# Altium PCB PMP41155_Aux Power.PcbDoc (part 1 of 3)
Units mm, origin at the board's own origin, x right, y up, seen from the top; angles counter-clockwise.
Board outline 40.5 x 70.5 mm, 6 copper layers (Top Layer, Signal Layer 1, Signal Layer 2, Signal Layer 3, Signal Layer 4, Bottom Layer), stack 1.573 mm thick; 130 components, 63 nets, 392 pads, 295 vias.
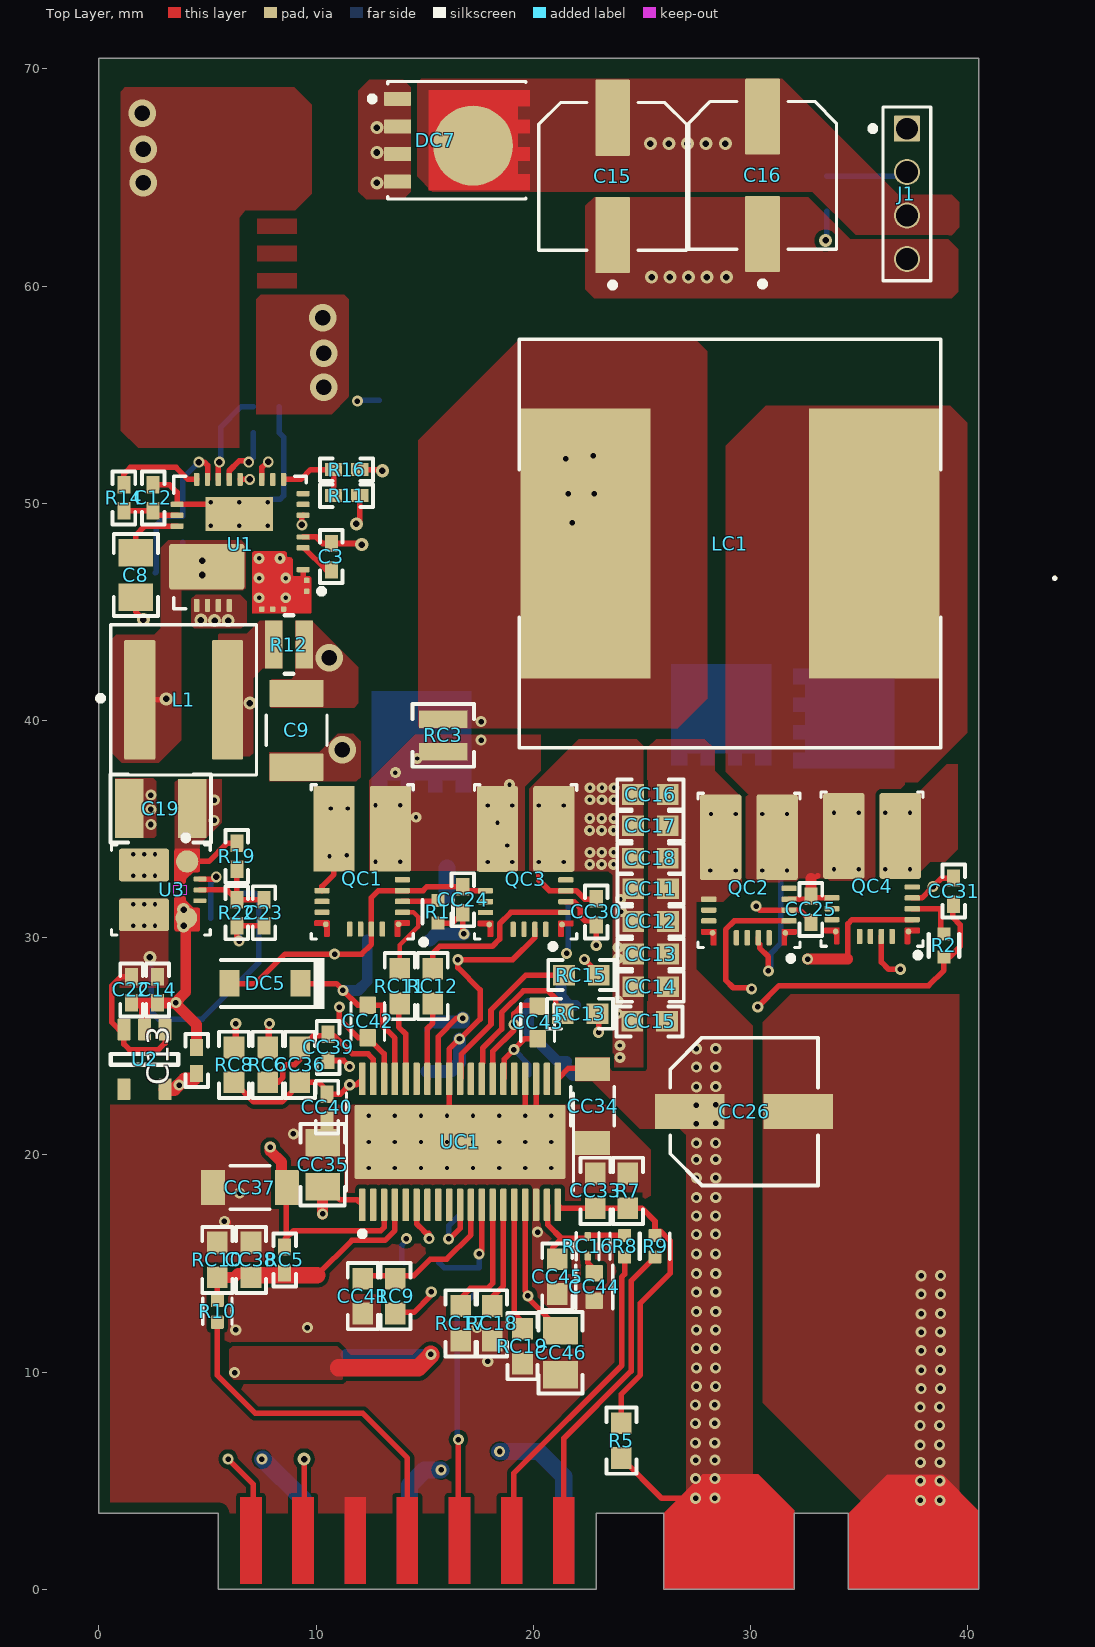
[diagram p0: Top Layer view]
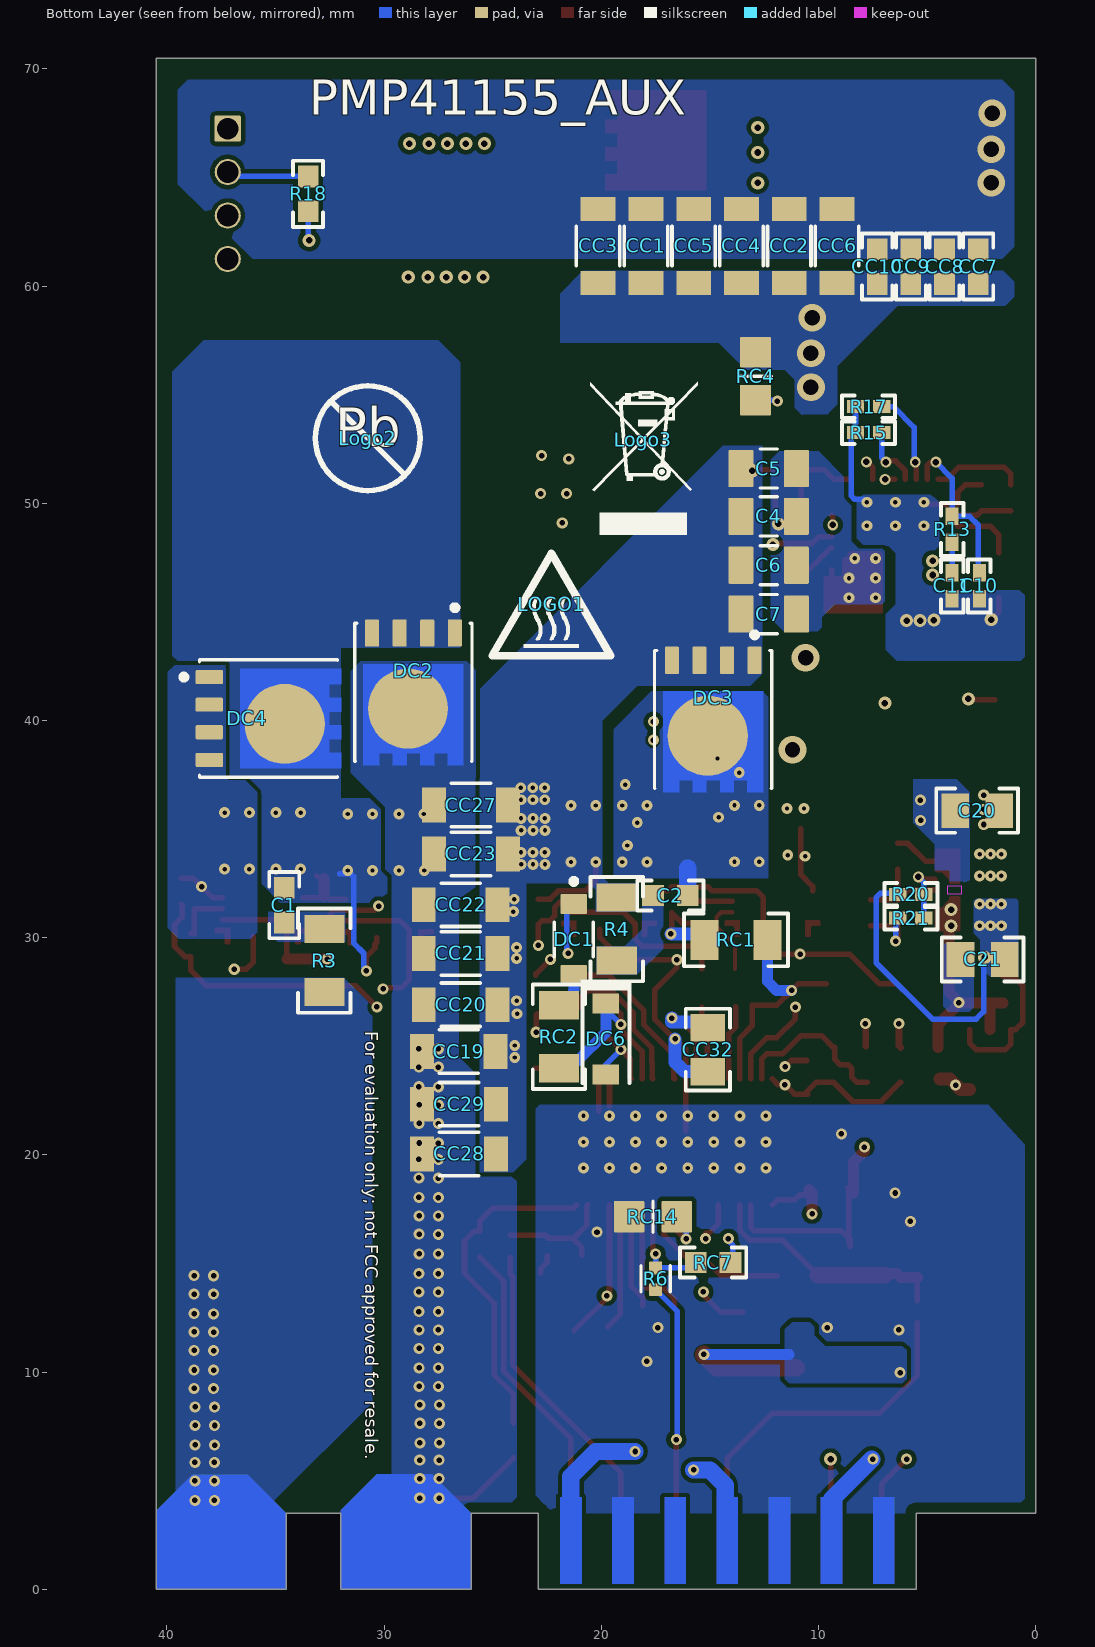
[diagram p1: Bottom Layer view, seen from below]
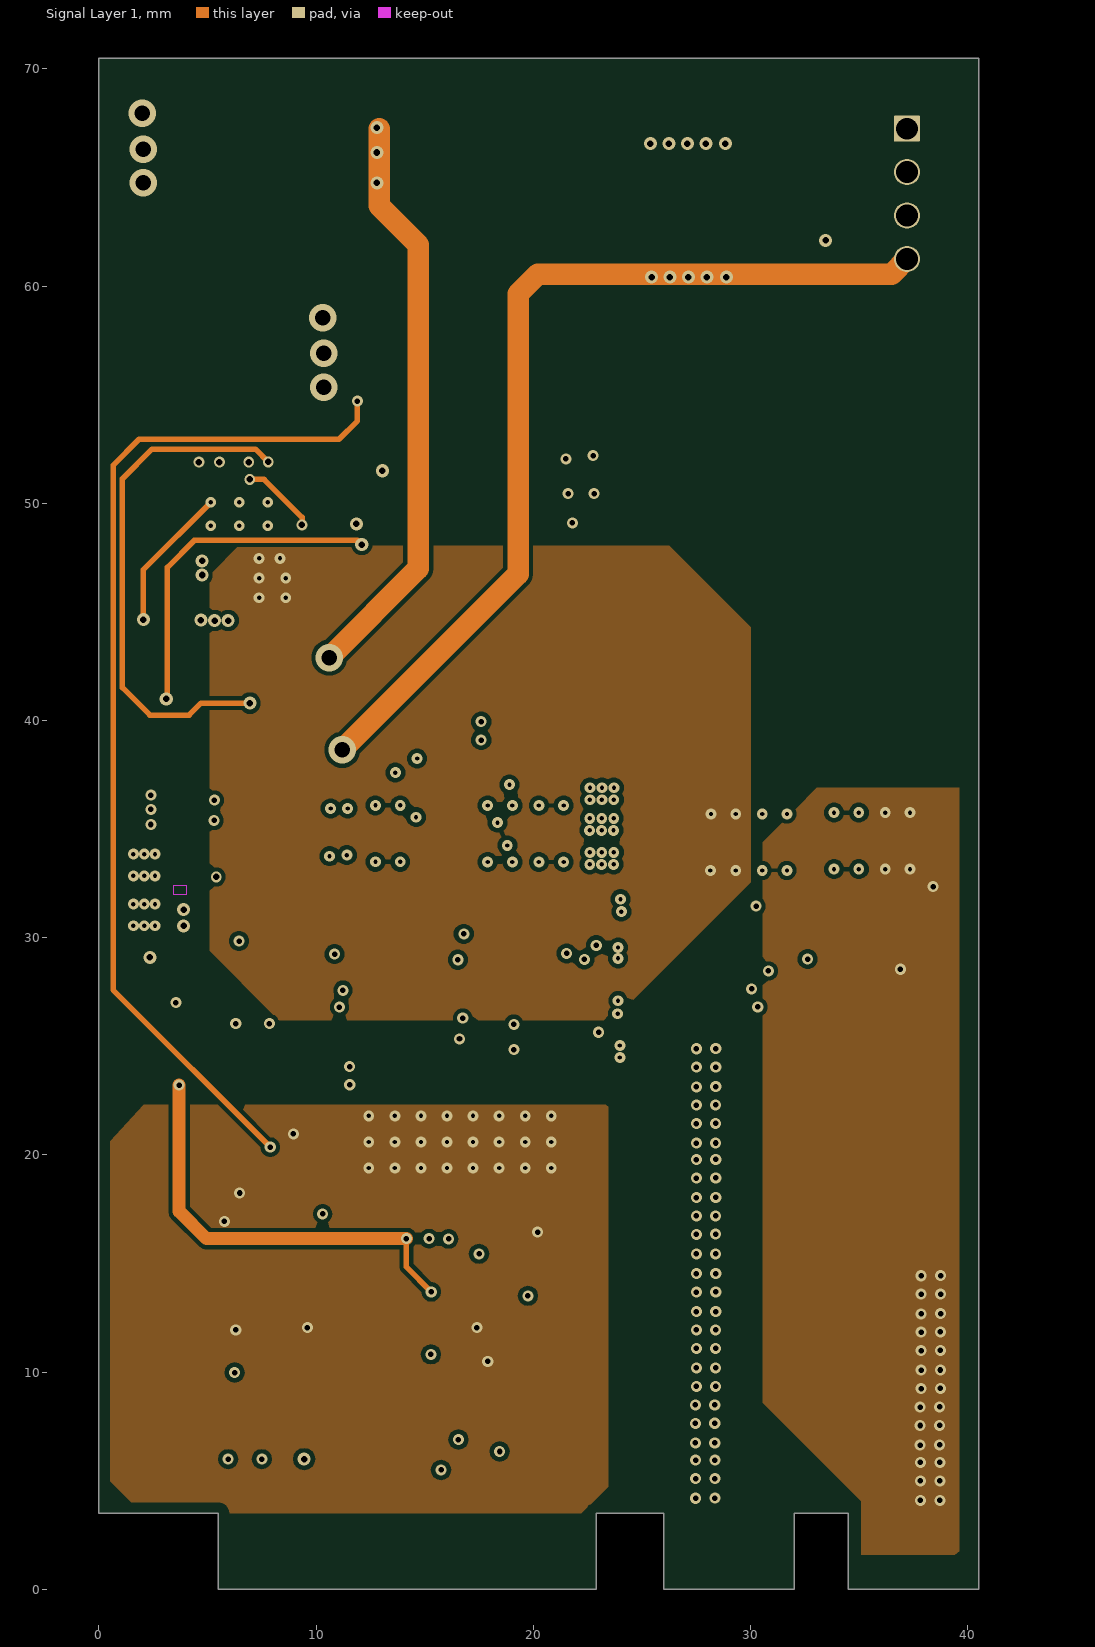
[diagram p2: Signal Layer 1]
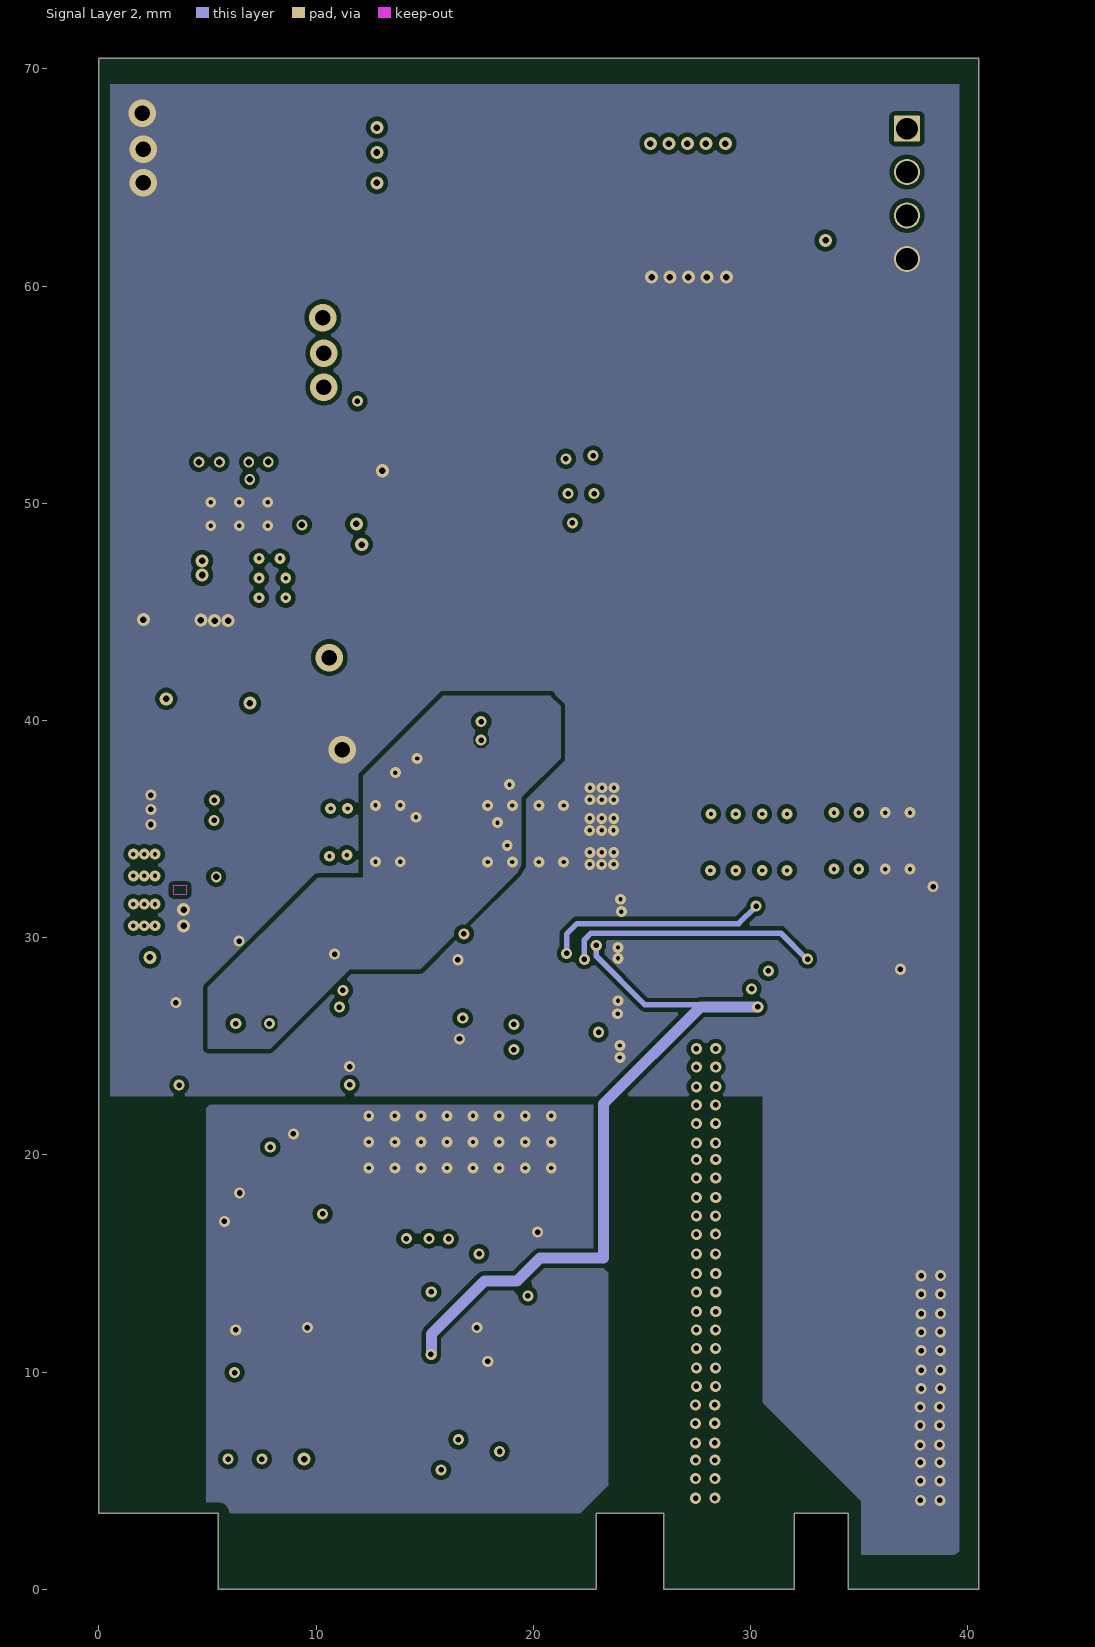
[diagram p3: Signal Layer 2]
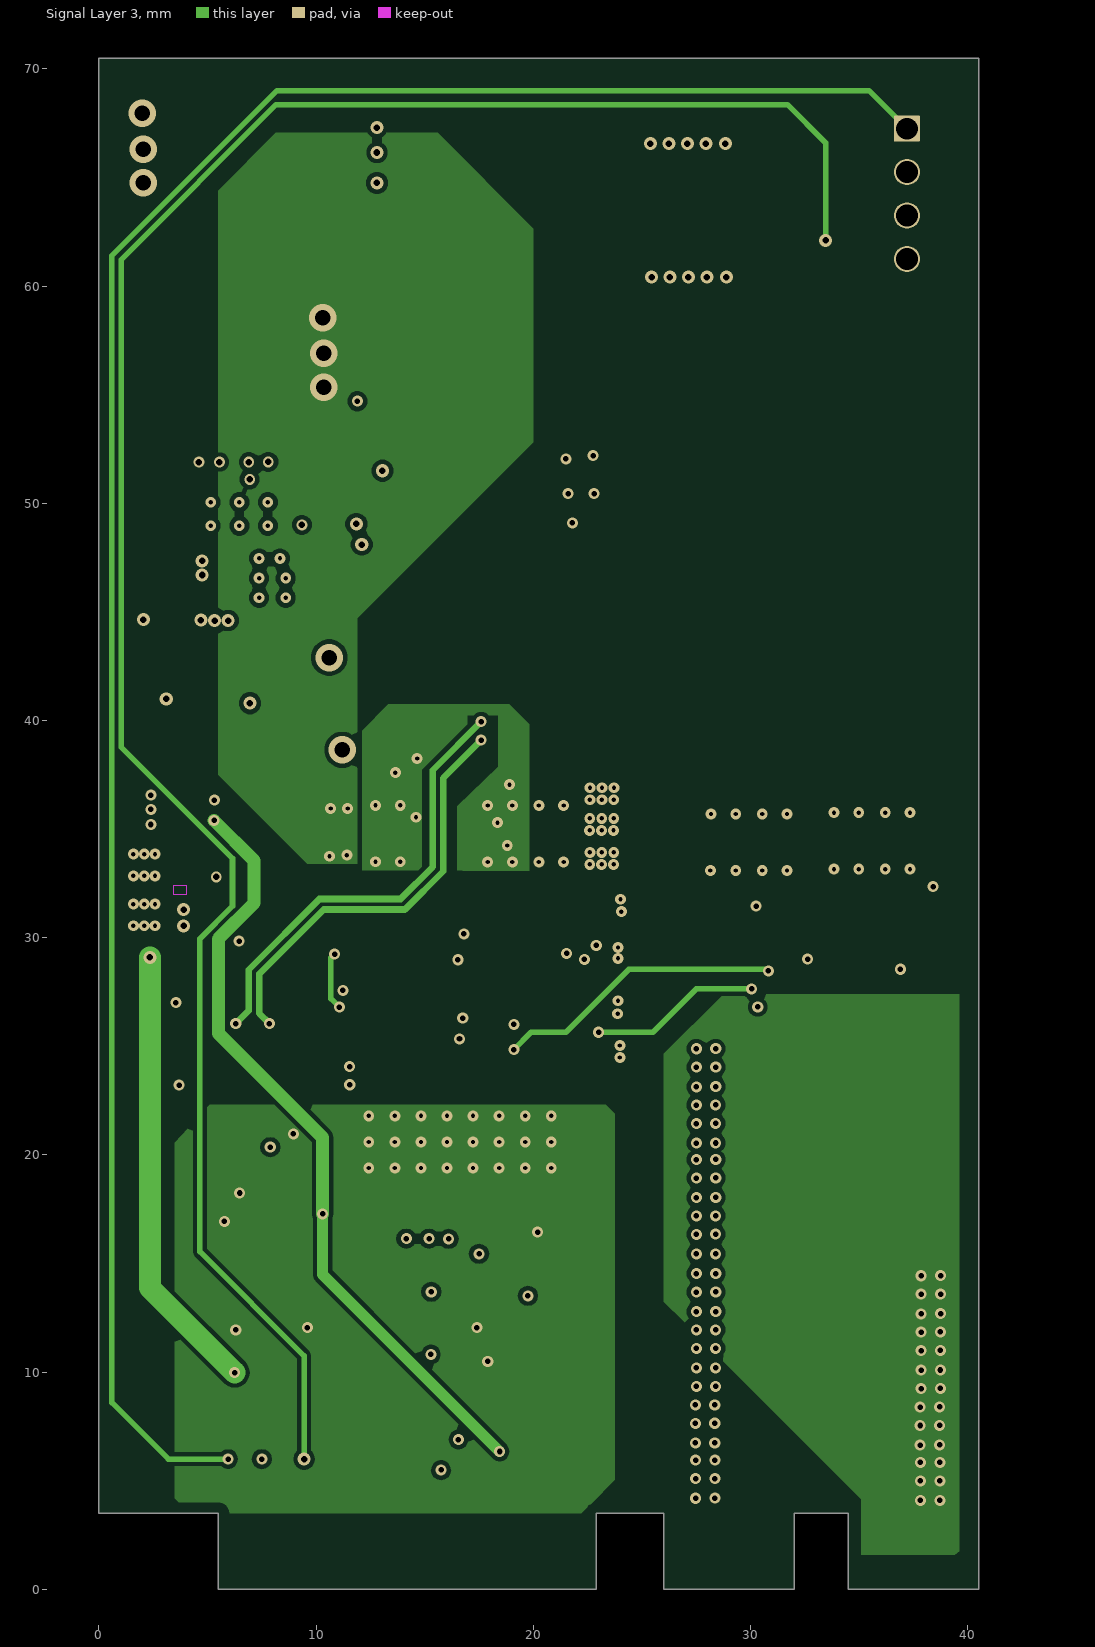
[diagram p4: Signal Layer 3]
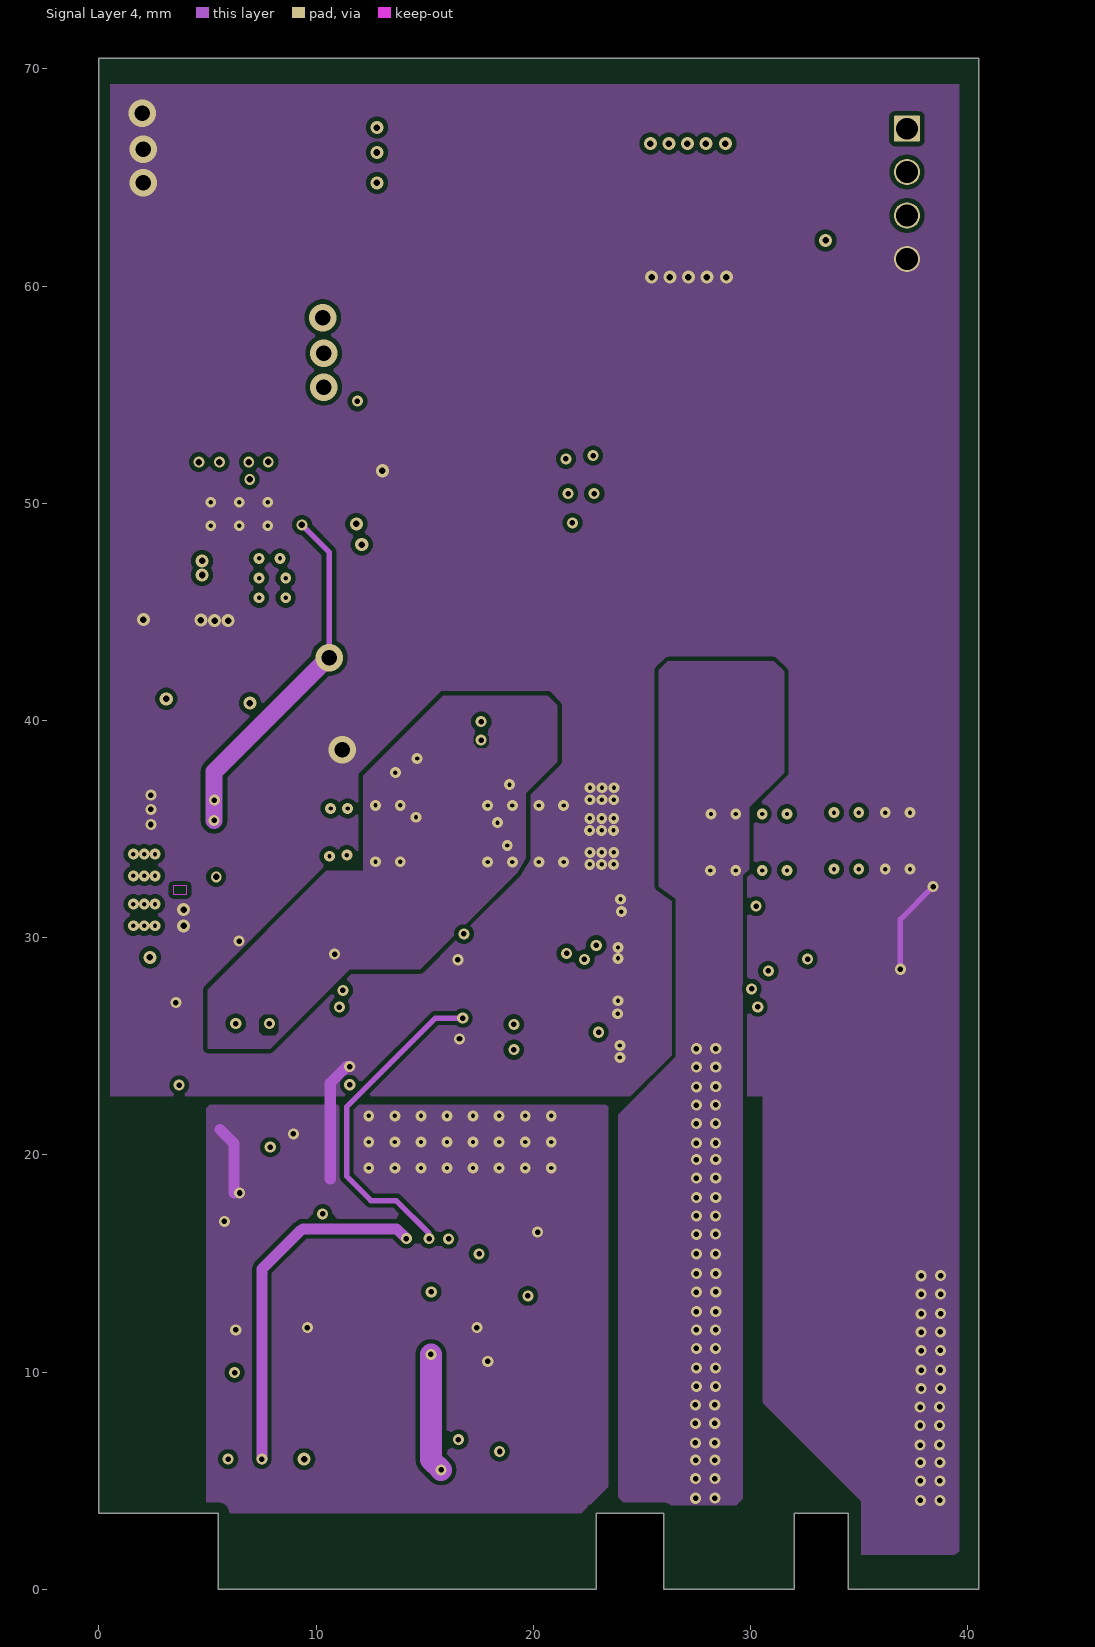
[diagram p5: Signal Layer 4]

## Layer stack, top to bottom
Top Solder: solder mask 0.01, Solder Resist, Dk 3.5
Top Layer: signal copper 0.07
Dielectric 1: prepreg 0.2, FR-4, Dk 4.2
Signal Layer 1: signal copper 0.07
Dielectric 4: core 0.2, FR-4, Dk 4.2
Signal Layer 2: signal copper 0.07
Dielectric 2: core 0.2, FR-4, Dk 4.2
Signal Layer 3: signal copper 0.07
Dielectric1: core 0.2032, Core-025, Dk 4.6
Signal Layer 4: signal copper 0.07
Dielectric 3: prepreg 0.35, Dk 4.2
Bottom Layer: signal copper 0.07
Bottom Solder: solder mask 0.01, Solder Resist, Dk 3.5

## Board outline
0,3.5 5.5,3.5 5.5,0 22.9,0 22.9,3.5 26,3.5 26,0 32,0 32,3.5 34.5,3.5 34.5,0 40.5,0 40.5,70.5 0,70.5

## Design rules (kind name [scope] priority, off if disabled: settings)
AcuteAngle [All] p1: minimum=4.50000000000000E+0001 checktracksonly=FALSE
AssemblyTestPointUsage [All] p1: valid=2
BoardOutlineClearance BoardOutlineClearance_MountingHoles [OnCopper and InComponentClass('Mounting Holes')] p1: gap=1.016 ignorepadtopadclearanceinfootprint=FALSE
BoardOutlineClearance BoardOutlineClearance_Poly [OnCopper and IsPoly] p2: gap=0.508 ignorepadtopadclearanceinfootprint=FALSE
BoardOutlineClearance [OnCopper and Not InComponentClass('Logo') and not InComponentClass('FiducialMark') and not InRegion(1000,500,4000,800) and not InPoly] p3: gap=0.254 ignorepadtopadclearanceinfootprint=FALSE
Clearance Clearance_1 [InNetClass('HV') vs Not InNetClass('HV')] p1: gap=0.508 ignorepadtopadclearanceinfootprint=FALSE
Clearance Clearance_Keepouts [((IsTrack Or IsArc) And Not InPoly) And IsFree and IsKeepOut vs ((IsTrack Or IsArc) And Not InPoly) And IsFree and IsKeepOut] p2: gap=0 ignorepadtopadclearanceinfootprint=FALSE
Clearance Clearance_Poly [InPolygon] p3: gap=0.2 ignorepadtopadclearanceinfootprint=FALSE
Clearance Clearance_FiducialMark [IsKeepOut and InComponentClass('FiducialMark') vs IsPad and InComponentClass('FiducialMark')] p4: gap=0 ignorepadtopadclearanceinfootprint=FALSE
Clearance [All] p5: gap=0.178 ignorepadtopadclearanceinfootprint=FALSE except(0.1: Via-Via Via-Fill Via-Poly Via-Region Via-Text Via-Hole)
ComponentClearance ComponentClearance_MountingHoles_FiducialMarks [InComponentClass('Mounting Holes') vs InComponentClass('FiducialMark')] p1: gap=1.27 collisioncheckmode=3 verticalgap=0.254 showdistances=FALSE
ComponentClearance ComponentClearance_Shunt [InComponentClass('Header') vs InComponentClass('Shunt')] p2: gap=0 collisioncheckmode=3 verticalgap=0 showdistances=FALSE
ComponentClearance ComponentClearance_Logo [InComponentClass('Logo')] p3: gap=1.27 collisioncheckmode=3 verticalgap=0.254 showdistances=FALSE
ComponentClearance ComponentClearance_ScrewToNut [(HasFootprint('NY PMS 440 0025 PH')) vs (HasFootprint('Keystone_1902C'))] p4: gap=0.127 collisioncheckmode=3 verticalgap=0.254 showdistances=FALSE
ComponentClearance ComponentClearance_MountingHoles [InComponentClass('Mounting Holes')] p5: gap=6.35 collisioncheckmode=3 verticalgap=2540 showdistances=FALSE
ComponentClearance ComponentClearance_SmallPassives [HasFootprint('0201*') or HasFootprint('0402*') or HasFootprint('0508') or HasFootprint('0603*') or HasFootprint('0612') or HasFootprint('0805*') or HasFootprint('0815*') or HasFootprint('0830*') or HasFootprint('1206*') or HasFootprint('1210*') or HasFootprint('1808*') or HasFootprint('1812*') or HasFootprint('1825*') or HasFootprint('2010*') or HasFootprint('2220*') or HasFootprint('2225*') or HasFootprint('2512*') or HasFootprint('2728*') or HasFootprint('3518*') vs HasFootprint('0201*') or HasFootprint('0402*') or HasFootprint('0508') or HasFootprint('0603*') or HasFootprint('0612') or HasFootprint('0805*') or HasFootprint('0815*') or HasFootprint('0830*') or HasFootprint('1206*') or HasFootprint('1210*') or HasFootprint('1808*') or HasFootprint('1812*') or HasFootprint('1825*') or HasFootprint('2010*') or HasFootprint('2220*') or HasFootprint('2225*') or HasFootprint('2512*') or HasFootprint('2728*') or HasFootprint('3518*')] p6: gap=0.254 collisioncheckmode=3 verticalgap=0.254 showdistances=FALSE
ComponentClearance ComponentClearance_THtoSMT [IsThruComponent vs IsSMTComponent] p7: gap=1.016 collisioncheckmode=3 verticalgap=0.762 showdistances=FALSE
ComponentClearance ComponentClearance_THtoTH [IsThruComponent vs IsThruComponent] p8: gap=0.508 collisioncheckmode=3 verticalgap=0.508 showdistances=FALSE
ComponentClearance [All] p9: gap=0.254 collisioncheckmode=3 verticalgap=0.254 showdistances=FALSE
DiffPairsRouting [All] p1: maxlimit=2.54 minlimit=0.254 mostfreqgap=0.254 toplayer_minwidth=0.381 toplayer_maxwidth=0.381 toplayer_prefwidth=0.381 midlayer1_minwidth=0.381 midlayer1_maxwidth=0.381 midlayer1_prefwidth=0.381 midlayer2_minwidth=0.381 midlayer2_maxwidth=0.381 midlayer2_prefwidth=0.381 midlayer3_minwidth=0.381 midlayer3_maxwidth=0.381 midlayer3_prefwidth=0.381 midlayer4_minwidth=0.381 midlayer4_maxwidth=0.381 midlayer4_prefwidth=0.381 bottomlayer_minwidth=0.381 bottomlayer_maxwidth=0.381 bottomlayer_prefwidth=0.381 maxuncoupledlength=25.4
FabricationTestPointUsage TestPointUsage [All] p1: valid=2 allowmultiple=FALSE
FabricationTestpoint Testpoint [All] p1: side=3 testpointundercomponent=TRUE minsize=1.016 maxsize=2.54 preferedsize=1.524 minholesize=0 maxholesize=1.016 preferedholesize=0.813 testpointgrid=0.025 allowsidetop=TRUE allowsidebottom=TRUE usegrid=TRUE gridtolerance=0
FanoutControl Fanout_LCC [IsLCC] p1: bgadir=Out bgaviamode=Centered fanoutstyle=Auto fanoutdirection=Alternating viagrid=0.025 // Fanout_LCC (Default Rule)
FanoutControl Fanout_BGA [IsBGA] p2: bgadir=Out bgaviamode=Centered fanoutstyle=Auto fanoutdirection=Alternating viagrid=0.025 // Fanout_BGA (Default Rule)
FanoutControl Fanout_Default [All] p4: bgadir=Out bgaviamode=Centered fanoutstyle=Auto fanoutdirection=Alternating viagrid=0.025 // Fanout_Default (Default Rule)
FanoutControl Fanout_Small [(CompPinCount < 5)] p5: bgadir=Out bgaviamode=Centered fanoutstyle=Auto fanoutdirection=OutThenIn viagrid=0.025 // Fanout_Small (Default Rule)
HoleSize [All] p1: absolutevalues=TRUE maxlimit=6.375 minlimit=0.2 maxpercent=80.000 minpercent=20.000
MinimumAnnularRing MinimumAnnularRing_ThermalPadVias [IsVia and InAnyComponent] p1: minimumring=0.15
MinimumAnnularRing [All] p2: minimumring=0.127
MinimumSolderMaskSliver MinimumSolderMaskSliver_Logo [InComponentClass('Logo') vs InComponentClass('Logo')] p1: minsoldermaskwidth=0.018
MinimumSolderMaskSliver [All] p2: minsoldermaskwidth=0.1
PlaneConnect [All] p1: planeconnectstyle=Direct reliefexpansion=0.254 reliefentries=4 reliefconductorwidth=0.254 reliefairgap=0.254
PolygonConnect PolygonConnect_19 [All vs IsNamedPolygon('SGND') Or  IsNamedPolygon('SGND') Or  IsNamedPolygon('SGND') Or  IsNamedPolygon('SW2') Or  IsNamedPolygon('VBAT_DISCH_IN') Or  IsNamedPolygon('VBAT_DISCH_IN') Or  IsNamedPolygon('VBAT_DISCH_IN') Or  IsNamedPolygon('CSB_DISCH') Or  IsNamedPolygon('SGND') Or  IsNamedPolygon('5V') Or  IsNamedPolygon('SGND') Or  IsNamedPolygon('SNGD') Or  IsNamedPolygon('SGND') Or  IsNamedPolygon('SGND') Or  IsNamedPolygon('SW2') Or  IsNamedPolygon('SGND') Or  IsNamedPolygon('SGND') Or  IsNamedPolygon('CSA_DISCH') Or  IsNamedPolygon('48V_DISCH_OUT') Or  IsNamedPolygon('VBAT_DISCH_IN') Or  IsNamedPolygon('SGND') Or  IsNamedPolygon('SGND') Or  IsNamedPolygon('48V_DISCH_OUT') Or  IsNamedPolygon('SGND') Or  IsNamedPolygon('CSA_DISCH') Or  IsNamedPolygon('5V') Or  IsNamedPolygon('SGND') Or  IsNamedPolygon('SGND') Or  IsNamedPolygon('48V_DISCH_OUT') Or  IsNamedPolygon('48V_DISCH_OUT') Or  IsNamedPolygon('SGND') Or  IsNamedPolygon('12V_AUX') Or  IsNamedPolygon('48V_DISCH_OUT') Or  IsNamedPolygon('VBAT_DISCH_IN') Or  IsNamedPolygon('VBAT_DISCH_IN') Or  IsNamedPolygon('SGND')] p1: connectstyle=Direct reliefconductorwidth=0.254 reliefentries=4 polygonreliefangle="90 Angle" airgapwidth=0.254
PolygonConnect PolygonConnect_18 [All vs IsNamedPolygon('SW2') Or  IsNamedPolygon('VBAT_DISCH_IN') Or  IsNamedPolygon('VBAT_DISCH_IN') Or  IsNamedPolygon('VBAT_DISCH_IN') Or  IsNamedPolygon('48V_DISCH_OUT') Or  IsNamedPolygon('VBAT_DISCH_IN') Or  IsNamedPolygon('SGND') Or  IsNamedPolygon('SGND') Or  IsNamedPolygon('SGND') Or  IsNamedPolygon('SGND') Or  IsNamedPolygon('SGND') Or  IsNamedPolygon('VBAT_DISCH_IN') Or  IsNamedPolygon('SGND') Or  IsNamedPolygon('CSA_DISCH') Or  IsNamedPolygon('SGND') Or  IsNamedPolygon('48V_DISCH_OUT') Or  IsNamedPolygon('48V_DISCH_OUT') Or  IsNamedPolygon('5V') Or  IsNamedPolygon('SGND') Or  IsNamedPolygon('SGND') Or  IsNamedPolygon('SGND') Or  IsNamedPolygon('SGND') Or  IsNamedPolygon('12V_AUX') Or  IsNamedPolygon('CSA_DISCH') Or  IsNamedPolygon('CSB_DISCH') Or  IsNamedPolygon('SGND') Or  IsNamedPolygon('SGND') Or  IsNamedPolygon('VBAT_DISCH_IN')] p2: connectstyle=Direct reliefconductorwidth=0.254 reliefentries=4 polygonreliefangle="90 Angle" airgapwidth=0.254
PolygonConnect PolygonConnect_17 [All vs IsNamedPolygon('SGND') Or  IsNamedPolygon('VBAT_DISCH_IN') Or  IsNamedPolygon('SGND') Or  IsNamedPolygon('VBAT_DISCH_IN') Or  IsNamedPolygon('CSA_DISCH') Or  IsNamedPolygon('VBAT_DISCH_IN') Or  IsNamedPolygon('VBAT_DISCH_IN') Or  IsNamedPolygon('SGND') Or  IsNamedPolygon('SGND') Or  IsNamedPolygon('48V_DISCH_OUT') Or  IsNamedPolygon('CSA_DISCH') Or  IsNamedPolygon('SGND') Or  IsNamedPolygon('VBAT_DISCH_IN') Or  IsNamedPolygon('SGND') Or  IsNamedPolygon('5V') Or  IsNamedPolygon('48V_DISCH_OUT') Or  IsNamedPolygon('SGND') Or  IsNamedPolygon('CSB_DISCH') Or  IsNamedPolygon('SW2') Or  IsNamedPolygon('SGND') Or  IsNamedPolygon('48V_DISCH_OUT') Or  IsNamedPolygon('SGND') Or  IsNamedPolygon('VBAT_DISCH_IN')] p3: connectstyle=Direct reliefconductorwidth=0.254 reliefentries=4 polygonreliefangle="90 Angle" airgapwidth=0.254
PolygonConnect PolygonConnect_16 [All vs IsNamedPolygon('SGND') Or  IsNamedPolygon('SGND') Or  IsNamedPolygon('CSA_DISCH') Or  IsNamedPolygon('48V_DISCH_OUT') Or  IsNamedPolygon('VBAT_DISCH_IN') Or  IsNamedPolygon('SGND') Or  IsNamedPolygon('SGND') Or  IsNamedPolygon('SGND') Or  IsNamedPolygon('SGND') Or  IsNamedPolygon('VBAT_DISCH_IN') Or  IsNamedPolygon('VBAT_DISCH_IN') Or  IsNamedPolygon('CSB_DISCH') Or  IsNamedPolygon('SGND') Or  IsNamedPolygon('VBAT_DISCH_IN') Or  IsNamedPolygon('VBAT_DISCH_IN') Or  IsNamedPolygon('SGND') Or  IsNamedPolygon('VBAT_DISCH_IN') Or  IsNamedPolygon('SW2') Or  IsNamedPolygon('CSA_DISCH') Or  IsNamedPolygon('SGND')] p4: connectstyle=Direct reliefconductorwidth=0.254 reliefentries=4 polygonreliefangle="90 Angle" airgapwidth=0.254
PolygonConnect PolygonConnect_15 [All vs IsNamedPolygon('CSA_DISCH') Or  IsNamedPolygon('SGND') Or  IsNamedPolygon('SGND') Or  IsNamedPolygon('48V_DISCH_OUT') Or  IsNamedPolygon('VBAT_DISCH_IN') Or  IsNamedPolygon('SW2') Or  IsNamedPolygon('VBAT_DISCH_IN') Or  IsNamedPolygon('SGND') Or  IsNamedPolygon('VBAT_DISCH_IN') Or  IsNamedPolygon('CSB_DISCH') Or  IsNamedPolygon('VBAT_DISCH_IN') Or  IsNamedPolygon('CSA_DISCH') Or  IsNamedPolygon('VBAT_DISCH_IN')] p5: connectstyle=Direct reliefconductorwidth=0.254 reliefentries=4 polygonreliefangle="90 Angle" airgapwidth=0.254
PolygonConnect PolygonConnect_14 [All vs IsNamedPolygon('SW2') Or  IsNamedPolygon('48V_DISCH_OUT') Or  IsNamedPolygon('SGND') Or  IsNamedPolygon('SGND') Or  IsNamedPolygon('CSA_DISCH') Or  IsNamedPolygon('CSB_DISCH')] p6: connectstyle=Direct reliefconductorwidth=0.254 reliefentries=4 polygonreliefangle="90 Angle" airgapwidth=0.254
PolygonConnect PolygonConnect_13 [All vs IsNamedPolygon('SGND') Or  IsNamedPolygon('48V_DISCH_OUT') Or  IsNamedPolygon('SGND') Or  IsNamedPolygon('CSB_DISCH') Or  IsNamedPolygon('CSA_DISCH')] p7: connectstyle=Direct reliefconductorwidth=0.254 reliefentries=4 polygonreliefangle="90 Angle" airgapwidth=0.254
PolygonConnect PolygonConnect_12 [All vs IsNamedPolygon('48V_DISCH_OUT') Or  IsNamedPolygon('SGND') Or  IsNamedPolygon('SGND')] p8: connectstyle=Direct reliefconductorwidth=0.254 reliefentries=4 polygonreliefangle="90 Angle" airgapwidth=0.254
PolygonConnect PolygonConnect_11 [All vs IsNamedPolygon('GND') Or  IsNamedPolygon('D101_2') Or  IsNamedPolygon('V+') Or  IsNamedPolygon('GND') Or  IsNamedPolygon('C128_1') Or  IsNamedPolygon('J2_2') Or  IsNamedPolygon('CS') Or  IsNamedPolygon('V+') Or  IsNamedPolygon('GND') Or  IsNamedPolygon('J2_2') Or  IsNamedPolygon('PGND') Or  IsNamedPolygon('12V') Or  IsNamedPolygon('PGND') Or  IsNamedPolygon('PGND') Or  IsNamedPolygon('V+') Or  IsNamedPolygon('V+') Or  IsNamedPolygon('D101_2') Or  IsNamedPolygon('CS') Or  IsNamedPolygon('GND')] p9: connectstyle=Direct reliefconductorwidth=0.254 reliefentries=4 polygonreliefangle="90 Angle" airgapwidth=0.254
PolygonConnect PolygonConnect_10 [All vs IsNamedPolygon('GND') Or  IsNamedPolygon('C128_1') Or  IsNamedPolygon('GND') Or  IsNamedPolygon('J2_2') Or  IsNamedPolygon('GND') Or  IsNamedPolygon('D101_2') Or  IsNamedPolygon('J2_2') Or  IsNamedPolygon('V+') Or  IsNamedPolygon('PGND') Or  IsNamedPolygon('CS') Or  IsNamedPolygon('V+')] p10: connectstyle=Direct reliefconductorwidth=0.254 reliefentries=4 polygonreliefangle="90 Angle" airgapwidth=0.254
PolygonConnect PolygonConnect_9 [All vs IsNamedPolygon('J2_2') Or  IsNamedPolygon('GND') Or  IsNamedPolygon('8V5') Or  IsNamedPolygon('V+') Or  IsNamedPolygon('R117_1') Or  IsNamedPolygon('PGND') Or  IsNamedPolygon('PGND') Or  IsNamedPolygon('Drv') Or  IsNamedPolygon('V+') Or  IsNamedPolygon('V+') Or  IsNamedPolygon('C128_1') Or  IsNamedPolygon('GND') Or  IsNamedPolygon('GND') Or  IsNamedPolygon('J2_2') Or  IsNamedPolygon('PGND')] p11: connectstyle=Direct reliefconductorwidth=0.254 reliefentries=4 polygonreliefangle="90 Angle" airgapwidth=0.254
PolygonConnect PolygonConnect_8 [All vs IsNamedPolygon('8V5') Or  IsNamedPolygon('J2_2') Or  IsNamedPolygon('PGND') Or  IsNamedPolygon('GND') Or  IsNamedPolygon('GND') Or  IsNamedPolygon('V+') Or  IsNamedPolygon('J2_2') Or  IsNamedPolygon('V+') Or  IsNamedPolygon('C128_1') Or  IsNamedPolygon('V+') Or  IsNamedPolygon('PGND') Or  IsNamedPolygon('J2_2') Or  IsNamedPolygon('J2_2') Or  IsNamedPolygon('R117_1')] p12: connectstyle=Direct reliefconductorwidth=0.254 reliefentries=4 polygonreliefangle="90 Angle" airgapwidth=0.254
PolygonConnect PolygonConnect_7 [All vs IsNamedPolygon('J2_2') Or  IsNamedPolygon('J2_2') Or  IsNamedPolygon('J2_2') Or  IsNamedPolygon('C128_1') Or  IsNamedPolygon('J2_2')] p13: connectstyle=Direct reliefconductorwidth=0.254 reliefentries=4 polygonreliefangle="90 Angle" airgapwidth=0.254
PolygonConnect PolygonConnect_6 [All vs IsNamedPolygon('J2_2')] p14: connectstyle=Direct reliefconductorwidth=0.254 reliefentries=4 polygonreliefangle="90 Angle" airgapwidth=0.254
PolygonConnect PolygonConnect_5 [All vs IsNamedPolygon('GND') Or  IsNamedPolygon('Vout') Or  IsNamedPolygon('Bottom Layer-SW') Or  IsNamedPolygon('GND') Or  IsNamedPolygon('C1_1') Or  IsNamedPolygon('Q1_3') Or  IsNamedPolygon('J2_2') Or  IsNamedPolygon('GND') Or  IsNamedPolygon('J2_2') Or  IsNamedPolygon('GND') Or  IsNamedPolygon('Vout') Or  IsNamedPolygon('Top Layer-SW') Or  IsNamedPolygon('Q1_3') Or  IsNamedPolygon('GND') Or  IsNamedPolygon('J2_2') Or  IsNamedPolygon('J2_2') Or  IsNamedPolygon('GND') Or  IsNamedPolygon('GND') Or  IsNamedPolygon('GND') Or  IsNamedPolygon('GND') Or  IsNamedPolygon('GND')] p15: connectstyle=Direct reliefconductorwidth=0.254 reliefentries=4 polygonreliefangle="90 Angle" airgapwidth=0.254
PolygonConnect PolygonConnect_4 [All vs IsNamedPolygon('GND') Or  IsNamedPolygon('Bottom Layer-SW') Or  IsNamedPolygon('C1_1') Or  IsNamedPolygon('Top Layer-SW') Or  IsNamedPolygon('GND') Or  IsNamedPolygon('GND') Or  IsNamedPolygon('GND') Or  IsNamedPolygon('Q1_3') Or  IsNamedPolygon('Vout') Or  IsNamedPolygon('Q1_3') Or  IsNamedPolygon('Vout')] p16: connectstyle=Direct reliefconductorwidth=0.254 reliefentries=4 polygonreliefangle="90 Angle" airgapwidth=0.254
PolygonConnect PolygonConnect_3 [All vs IsNamedPolygon('Q1_3') Or  IsNamedPolygon('Q1_3') Or  IsNamedPolygon('Top Layer-SW') Or  IsNamedPolygon('C1_1') Or  IsNamedPolygon('Bottom Layer-SW')] p17: connectstyle=Direct reliefconductorwidth=0.254 reliefentries=4 polygonreliefangle="90 Angle" airgapwidth=0.254
PolygonConnect PolygonConnect_2 [All vs IsNamedPolygon('Top Layer-SW') Or  IsNamedPolygon('Bottom Layer-SW')] p18: connectstyle=Direct reliefconductorwidth=0.254 reliefentries=4 polygonreliefangle="90 Angle" airgapwidth=0.254
PolygonConnect PolygonConnect_1 [All vs IsNamedPolygon('Bottom Layer-SW') Or  IsNamedPolygon('Top Layer-SW')] p19: thpad.connectstyle=Direct thpad.reliefconductorwidth=0.254 thpad.reliefentries=4 thpad.polygonreliefangle="90 Angle" thpad.airgapwidth=0.254 smdpad.connectstyle=Direct smdpad.reliefconductorwidth=0.254 smdpad.reliefentries=4 smdpad.polygonreliefangle="90 Angle" smdpad.airgapwidth=0.254 via.connectstyle=Relief via.reliefconductorwidth=0.254 via.reliefentries=4 via.polygonreliefangle="90 Angle" via.airgapwidth=0.254
PolygonConnect [All] p20: connectstyle=Direct reliefconductorwidth=0.254 reliefentries=4 polygonreliefangle="90 Angle" airgapwidth=0.254
RoutingVias ThermalPadVias [IsVia and InAnyComponent] p1: holewidth=0.2 width=0.5 viastyle="Through Hole" minholewidth=0.2 minwidth=0.5 maxholewidth=0.33 maxwidth=0.6
RoutingVias [All] p2: holewidth=0.254 width=0.508 viastyle="Through Hole" minholewidth=0.2 minwidth=0.508 maxholewidth=1.016 maxwidth=1.651
SilkToBoardRegionClearance [Not ((IsComment or IsDesignator) And (Hide <> 'False')) and not InRegion(1000,500,4000,800)] p1:
SilkToSilkClearance SilkToSilkClearance_Pb-FreeLogo [(HasFootprint('Pb-Free_Overlay_Medium') OR HasFootprint('Pb-Free_Overlay_Small')) vs (HasFootprint('Pb-Free_Overlay_Medium') OR HasFootprint('Pb-Free_Overlay_Small'))] p1: silktosilkclearance=0
SilkToSilkClearance [All] p2: silktosilkclearance=0.102
SilkToSolderMaskClearance SilkToComponentPadClearance [(IsPad or IsFill or IsRegion) and InAnycomponent] p1: minsilkscreentomaskgap=0.127 clearancetoexposedcopper=TRUE
SilkToSolderMaskClearance "Silk to Solder Mask Opening" [All] p2: minsilkscreentomaskgap=0.102 clearancetoexposedcopper=FALSE
SolderMaskExpansion [All] p1: expansion=0.05 istentingtop=FALSE
SupplyNets "Schematic Supply Nets" [InNet('VAUX')] p1: voltage=0.000
SupplyNets "Schematic Supply Nets_4" [InNet('12V')] p2: voltage=0.000
SupplyNets "Schematic Supply Nets_1" [InNet('SGND')] p3: voltage=0.000
Width [All] p1: maxlimit=2.54 minlimit=0.152 preferedwidth=0.254 checkconnectedcopper=TRUE
15 further rules are at their usual default settings.

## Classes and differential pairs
component class "PMP41155_Aux Power_D2D": C3 C4 C5 C6 C7 C8 C9 C10 C11 C12 C13 C14 C15 C16 C19 C20 C21 C22 C23 DC7 J1 L1 R11 R12 R13 R14 R15 R16 R17 R18 R19 R20 R21 R22 U1 U2 U3
component class "PMP41155_Aux Power": !PCB100 C1 C2 CC1 CC2 CC3 CC4 CC5 CC6 CC7 CC8 CC9 CC10 CC11 CC12 CC13 CC14 CC15 CC16 CC17 CC18 CC19 CC20 CC21 CC22 CC23 CC24 CC25 CC26 CC27 CC28 CC29 CC30 CC31 CC32 CC33 CC34 CC35 CC36 CC37 CC38 CC39 CC40 CC41 CC42 CC43 CC44 CC45 CC46 DC1 DC2 DC3 DC4 DC5 DC6 LC1 LOGO1 Logo2 Logo3 Logo4 QC1 QC2 QC3 QC4 R1 R2 R3 R4 R5 R6 R7 R8 R9 R10 RC1 RC2 RC3 RC4 RC5 RC6 RC7 RC8 RC9 RC10 RC11 RC12 RC13 RC14 RC15 RC16 RC17 RC18 RC19 UC1

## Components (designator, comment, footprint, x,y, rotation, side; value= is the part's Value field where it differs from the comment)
C1 "GRM188R72A182KA01D" 0603 34.6,31.5 r270 bottom value=1800pF
C2 "GRM188R72A182KA01D" 0603 16.823,31.945 r0 bottom value=1800pF
C3 "CGA2B3X7R1E104K050BB" 0402 10.7,47.55 r270 top value=0.1uF
C4 "CGA1206X7R475M101NT" FP-CGA1206X7R475M101NT_1206-IPC_C 12.3,49.4 r180 bottom value=4.7µF
C5 "CGA1206X7R475M101NT" FP-CGA1206X7R475M101NT_1206-IPC_C 12.3,51.6 r180 bottom value=4.7µF
C6 "CGA1206X7R475M101NT" FP-CGA1206X7R475M101NT_1206-IPC_C 12.3,47.15 r180 bottom value=4.7µF
C7 "CGA1206X7R475M101NT" FP-CGA1206X7R475M101NT_1206-IPC_C 12.3,44.9 r180 bottom value=4.7µF
C8 "CGA4J3X7R1C475K125AE" 0805_HV 1.7,46.7 r90 top value=4.7uF
C9 "EMK325ABJ476KMHP" FP-EMK325ABJ476KMHP_1210-MFG 9.1,39.55 r90 top value=47µF
C10 "CGA2B2NP01H470J050BA" 0402 2.6,46.2 r270 bottom value=47pF
C11 "CGA2B2X7R1H682K050BA" 0402 3.85,46.2 r270 bottom value=6800pF
C12 "CGA2B3X7R1E104K050BB" 0402 2.5,50.25 r90 top value=0.1uF
C13 "GRM152B30J104KE19" 0402 4.5,24.35 r90 top value=0.1uF
C14 "GRM152B30J104KE19" 0402 2.7,27.6 r270 top value=0.1uF
C15 "APXJ160ARA271MF80J" FP-APXJ160ARA271MF80J_SMT_CAP_6MM6_6MM6-MFG 23.65,65.05 r90 top value=270µF
C16 "APXJ160ARA271MF80J" FP-APXJ160ARA271MF80J_SMT_CAP_6MM6_6MM6-MFG 30.55,65.1 r90 top value=270µF
C19 "GRM32ER61C476KE15L" 1210_270 2.85,35.95 r180 top value=47uF
C20 "C0805C105K3RACTU" 0805_HV 2.7,35.85 r180 bottom value=1uF
C21 "CL21A226KQQNNNE" 0805_HV 2.45,29 r0 bottom value=22uF
C22 "GRM152B30J104KE19" 0402 1.5,27.6 r270 top value=0.1uF
C23 "C0402C103K4RACTU" 0402 7.6,31.15 r270 top value=0.01uF
CC1 "GRJ31CC72A475KE01L" 1206_180 17.95,61.85 r90 bottom value=4.7uF
CC2 "GRJ31CC72A475KE01L" 1206_180 11.35,61.85 r90 bottom value=4.7uF
CC3 "GRJ31CC72A475KE01L" 1206_180 20.15,61.85 r90 bottom value=4.7uF
CC4 "GRJ31CC72A475KE01L" 1206_180 13.55,61.85 r90 bottom value=4.7uF
CC5 "GRJ31CC72A475KE01L" 1206_180 15.75,61.85 r90 bottom value=4.7uF
CC6 "GRJ31CC72A475KE01L" 1206_180 9.15,61.85 r90 bottom value=4.7uF
CC7 "CGA3E2X7R2A223K080AA" 0603 2.65,60.9 r90 bottom value=0.022uF
CC8 "CGA3E2X7R2A223K080AA" 0603 4.2,60.9 r90 bottom value=0.022uF
CC9 "CGA3E2X7R2A223K080AA" 0603 5.75,60.9 r90 bottom value=0.022uF
CC10 "CGA3E2X7R2A223K080AA" 0603 7.3,60.9 r90 bottom value=0.022uF
CC11 "CGA3E2X7R2A223K080AA" 0603 25.4,32.25 r180 top value=0.022uF
CC12 "CGA3E2X7R2A223K080AA" 0603 25.4,30.75 r180 top value=0.022uF
CC13 "CGA3E2X7R2A223K080AA" 0603 25.4,29.25 r180 top value=0.022uF
CC14 "CGA3E2X7R2A223K080AA" 0603 25.4,27.75 r180 top value=0.022uF
CC15 "CGA3E2X7R2A223K080AA" 0603 25.35,26.15 r180 top value=0.022uF
CC16 "CGA3E2X7R2A223K080AA" 0603 25.386,36.594 r180 top value=0.022uF
CC17 "CGA3E2X7R2A223K080AA" 0603 25.386,35.152 r180 top value=0.022uF
CC18 "CGA3E2X7R2A223K080AA" 0603 25.386,33.652 r180 top value=0.022uF
CC19 "GRJ31CC72A475KE01L" 1206_180 26.565,24.76 r180 bottom value=4.7uF
CC20 "GRJ31CC72A475KE01L" 1206_180 26.474,26.914 r180 bottom value=4.7uF
CC21 "GRJ31CC72A475KE01L" 1206_180 26.474,29.279 r180 bottom value=4.7uF
CC22 "GRJ31CC72A475KE01L" 1206_180 26.474,31.515 r180 bottom value=4.7uF
CC23 "GRJ31CC72A475KE01L" 1206_180 26.003,33.858 r180 bottom value=4.7uF
CC24 "C0402C104K4RACAUTO" 0402 16.75,31.75 r90 top value=0.1uF
CC25 "C0402C104K4RACAUTO" 0402 32.776,31.304 r90 top value=0.1uF
CC26 "63PFV22M6.3X8" SM_RADIAL_D 29.7,22 r0 top value=22uF
CC27 "GRJ31CC72A475KE01L" 1206_180 26.003,36.108 r180 bottom value=4.7uF
CC28 "GRJ31CC72A475KE01L" 1206_180 26.55,20.05 r180 bottom value=4.7uF
CC29 "GRJ31CC72A475KE01L" 1206_180 26.552,22.34 r180 bottom value=4.7uF
CC30 "C0402C104K4RACAUTO" 0402 22.895,31.188 r90 top value=0.1uF
CC31 "C0402C104K4RACAUTO" 0402 39.35,32.15 r90 top value=0.1uF
CC32 "GRM21BR61A476ME15L" 0805_HV 15.1,24.85 r270 bottom value=47uF
CC33 "GRM188R71H221KA01D" 0603 22.855,18.35 r90 top value=220pF
CC34 "GRJ31CC72A475KE01L" 1206_180 22.728,22.245 r270 top value=4.7uF
CC35 "GRM219R61E225KA12D" 0805_HV 10.3,19.55 r270 top value=2.2uF
CC36 "06035A680JAT2A" 0603 9.25,24.15 r270 top value=68pF
CC37 "GRJ31CC72A475KE01L" 1206_180 6.95,18.5 r180 top value=4.7uF
CC38 "GRM1885C1H102JA01D" 0603 7,15.167 r90 top value=1000pF
CC39 "GRM1555C1H470FA01D" 0402 10.55,24.95 r270 top value=47pF
CC40 "GRM1555C1H470FA01D" 0402 10.5,22.2 r270 top value=47pF
CC41 "GRM188R61H222KA01D" 0603 12.15,13.5 r90 top value=2200pF
CC42 "0603YC104JAT2A" FP-0603YC104JAT2A_0603-MFG 12.375,26.15 r270 top value=100nF
CC43 "0603YC104JAT2A" FP-0603YC104JAT2A_0603-MFG 20.2,26.1 r270 top value=100nF
CC44 "CL10B223KB8NNNC" FP-CL10B223KB8NNNC_0603-IPC_C 22.8,13.923 r90 top value=22nF
CC45 "GRM1885C1E821JA01D" 0603 21.1,14.4 r270 top value=820pF
CC46 "08053C224MAT2A" 0805_HV 21.25,10.9 r270 top value=0.22uF
DC1 "NRVB0540T1G" FP-NRVB0540T1G_SOD-123-MFG 21.267,29.92 r270 bottom
DC2 "STPS30M100DJF-TR" FP-STPS30M100DJF-TR_PowerFlat6-MFG 28.65,41.3 r0 bottom
DC3 "STPS30M100DJF-TR" FP-STPS30M100DJF-TR_PowerFlat6-MFG 14.85,40.05 r0 bottom
DC4 "STPS30M100DJF-TR" FP-STPS30M100DJF-TR_PowerFlat6-MFG 35.325,40.095 r270 bottom
DC5 "MMSZ4690-E3-08" SOD-123 7.65,27.9 r180 top value=5.6V
DC6 "MMSZ4690-E3-08" SOD-123 19.787,25.341 r270 bottom value=5.6V
DC7 "STPS30M100DJF-TR" FP-STPS30M100DJF-TR_PowerFlat6-MFG 16.475,66.715 r270 top
J1 "831-87-004-10-001101" FP-831-87-004-10-001101_CONN_SOCKET_4-MFG 37.2,64.25 r270 top
L1 "XGL6060-332MEC" FP-XGL6060-332MEC_SMT_6MM51_6MM71-MFG 3.9,40.95 r0 top value=3.3uH
LC1 "TBD" WE-HCB_1890 29.05,48.15 r0 top
LOGO1 "CAUTION HOT SURFACE" IEC_HotSurface_Small 22.3,45.35 r180 bottom
Logo2 "Pb-Free Symbol" Pb-Free_Overlay_Medium 30.75,53 r180 bottom
Logo3 "WEEE logo" WEEE_Minimum 18.076,52.932 r180 bottom
Logo4 "FCC disclaimer" FCC_disclaimer 126.95,10.85 r90 bottom
QC1 "LMG3100R017" VBE0015A-MFG#1 12.12,33.497 r180 top
QC2 "LMG3100R017" VBE0015A-MFG#2 29.925,33.1 r180 top
QC3 "LMG3100R017" VBE0015A-MFG#2 19.645,33.488 r180 top
QC4 "LMG3100R017" VBE0015A-MFG#2 35.593,33.162 r180 top
R1 "CRCW04023R01FNED" FP-CRCW0402-e3-MFG 15.6,31.2 r90 top
R2 "CRCW04023R01FNED" FP-CRCW0402-e3-MFG 38.9,29.65 r270 top
R3 "CRCW12062R55FKEA" 1206 32.75,28.95 r90 bottom value=2.55
R4 "CRCW12062R55FKEA" 1206 19.287,30.4 r270 bottom value=2.55
R5 "CRCW0603681KFKEA" 0603 24.05,6.85 r270 top value=681k
R6 "D1LPC0402CJUMPF-T10" FP-D1LPC0402CJUMPF-T10_0402-MFG 17.5,14.3 r90 bottom value=0
R7 "CRCW060313K0FKEA" 0603 24.35,18.35 r270 top value=13.0k
R8 "D1LPC0402CJUMPF-T10" FP-D1LPC0402CJUMPF-T10_0402-MFG 24.2,15.8 r90 top value=0
R9 "D1LPC0402CJUMPF-T10" FP-D1LPC0402CJUMPF-T10_0402-MFG 25.6,15.8 r90 top value=0
R10 "D1LPC0402CJUMPF-T10" FP-D1LPC0402CJUMPF-T10_0402-MFG 5.45,12.8 r90 top value=0
R11 "RMCF0402FT100K" 0402 11.4,50.35 r0 top value=100k
R12 "KRL2012M-R005-F-T1" KRL2012 8.75,43.5 r0 top value=0.005
R13 "CRCW04025K76FKED" 0402 3.85,48.8 r90 bottom value=5.76k
R14 "MCR01MZPF4992" 0402 1.15,50.25 r90 top value=49.9k
R15 "CRCW040271K5FKED" 0402 7.7,53.25 r180 bottom value=71.5k
R16 "CRCW040220K5FKED" 0402 11.4,51.55 r180 top value=20.5k
R17 "CRCW040249K9FKED" 0402 7.7,54.45 r180 bottom value=49.9k
R18 "RC0603JR-070RL" 0603 33.5,64.25 r90 bottom value=0
R19 "CRCW040249K9FKED" 0402 6.35,33.75 r90 top value=49.9k
R20 "RC0402FR-07220KL" 0402 5.75,32 r0 bottom value=220k
R21 "CRCW040230K0FKED" 0402 5.75,30.9 r180 bottom value=30.0k
R22 "CRCW040230K0FKED" 0402 6.35,31.15 r90 top value=30.0k
RC1 "RC1206FR-073R3L" 1206 13.8,29.9 r0 bottom value=3.30
RC2 "RC1206FR-073R3L" 1206 21.95,25.444 r270 bottom value=3.30
RC3 "KRL2012E-M-R002-G-T5" 0508 15.85,39.313 r90 top value=0.002
RC4 "JR0805X35E" FP-JR0805X35E_0805-MFG 12.9,55.85 r270 bottom value=0
RC5 "CRCW040271K5FKED" 0402 8.55,15.167 r90 top value=71.5k
RC6 "RC0603FR-07100RL" 0603 7.77,24.15 r90 top value=100
RC7 "CRCW060310K0FKEA" 0603 14.85,15.05 r0 bottom value=10.0k
RC8 "RC0603FR-07100RL" 0603 6.22,24.15 r90 top value=100
RC9 "CRCW0603100RFKEA" 0603 13.65,13.5 r90 top value=100
RC10 "CRCW060310K7FKEA" 0603 5.45,15.167 r270 top value=10.7k
RC11 "CRCW06030000Z0EA" 0603 13.85,27.771 r90 top value=0
RC12 "CRCW06030000Z0EA" 0603 15.367,27.771 r90 top value=0
RC13 "CRCW06030000Z0EA" 0603 22.15,26.5 r0 top value=0
RC14 "JR0805X35E" FP-JR0805X35E_0805-MFG 17.625,17.16 r180 bottom value=0
RC15 "CRCW06030000Z0EA" 0603 22.209,28.281 r0 top value=0
RC16 "RK73H1ETTP2871F" FP-RK73H1ETTP2871F_0402-MFG 22.5,15.8 r90 top value=2.87k
RC17 "CRCW06038K25FKEA" 0603 16.65,12.25 r90 top value=8.25k
RC18 "CRCW0603100KFKEA" 0603 18.1,12.25 r90 top value=100k
RC19 "CRCW0603100KFKEA" 0603 19.5,11.2 r90 top value=100k
U1 "LM70880RRXRQ1" RRX0029B-MFG 6.5,48.2 r180 top
U2 "TLV71333PQDBVRQ1" DBV0005A_N 2.1,24.4 r270 top
U3 "TPSM863252RDX" RDX0007A-MFG 2.75,32.2 r270 top
UC1 "LM5177DCPR" DCP0038A-MFG 16.625,20.6 r90 top

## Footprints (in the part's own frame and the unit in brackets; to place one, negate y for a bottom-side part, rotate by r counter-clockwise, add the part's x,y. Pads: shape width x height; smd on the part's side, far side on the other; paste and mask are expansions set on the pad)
0402 [mm] "0402 from SM-752 data"
  rect 0.8x0.6 smd: 1(-0.6,0) 2(0.6,0)
  silkscreen extent -1.22,-0.52 1.22,0.52, body extent -0.55,-0.3 0.55,0.3, height 0.6
0508 [mm] "IPC nominal based on TDK C1220 type capacitors e4162_c.pdf"
  rect 0.8x2.25 smd: 1(-0.75,0) 2(0.75,0)
  silkscreen extent -1.44,-1.42 1.44,1.42, body extent -0.72,-1.1 0.72,1.1, height 1
0603 [mm] "0603 from SM-752 data"
  rect 1x0.95 smd: 1(-0.8,0) 2(0.8,0)
  silkscreen extent -1.52,-0.69 1.52,0.69, body extent -0.87,-0.47 0.87,0.47, height 1
0805_HV [mil] "0805 with 30mil clearance between pads"
  rect 50x63 smd: 1(-40,0) 2(40,0)
  silkscreen extent -74,-40 74,40, body extent -43,-29 43,29, height 57
1206 [mm] "1206 from SM-752 data"
  rect 1.3x1.85 smd: 1(-1.45,0) 2(1.45,0)
  silkscreen extent -2.4,-1.21 2.4,1.21, body extent -1.7,-0.9 1.7,0.9, height 1.35
1206_180 [mm] "1206_180"
  rect 1.1x1.6 smd: 1(-1.7,0) 2(1.7,0)
  silkscreen extent -0.9,-1 0.9,1, body extent -1.75,-0.95 1.75,0.95, height 1.8
1210_270 [mm] "1210"
  rect 1.3x2.7 smd: 1(-1.45,0) 2(1.45,0)
  silkscreen extent -2.32,-1.57 2.32,1.57, body extent -1.7,-1.35 1.7,1.35, height 2.7
DBV0005A_N [mm] "SOT23, 5-Leads, Body 2.9x1.6mm, Pitch 0.95mm, Lead Span 2.8mm, IPC Medium Density"
  rrect17% 1x0.6 smd: 1(-1.375,0.95) 2(-1.375,0) 3(-1.375,-0.95) 4(1.375,-0.95) 5(1.375,0.95)
  silkscreen extent -0.25,-1.55 0.25,1.55, body extent -1.42,-1.46 1.42,1.46, height 1.09
DCP0038A-MFG [mm]
  rrect33% 1.5x0.3 smd paste+0 mask+0: 1(-2.9,4.5) 2(-2.9,4) 3(-2.9,3.5) 4(-2.9,3) 5(-2.9,2.5) 6(-2.9,2) 7(-2.9,1.5) 8(-2.9,1) 9(-2.9,0.5) 10(-2.9,0) 11(-2.9,-0.5) 12(-2.9,-1) 13(-2.9,-1.5) 14(-2.9,-2) 15(-2.9,-2.5) 16(-2.9,-3) 17(-2.9,-3.5) 18(-2.9,-4) 19(-2.9,-4.5) 20(2.9,-4.5) 21(2.9,-4) 22(2.9,-3.5) 23(2.9,-3) 24(2.9,-2.5) 25(2.9,-2) 26(2.9,-1.5) 27(2.9,-1) 28(2.9,-0.5) 29(2.9,0) 30(2.9,0.5) 31(2.9,1) 32(2.9,1.5) 33(2.9,2) 34(2.9,2.5) 35(2.9,3) 36(2.9,3.5) 37(2.9,4) 38(2.9,4.5)
  rrect3% 3.4x9.7 smd paste-1000 mask-1000: 39(0,0)
  silkscreen extent -4.35,-5.23 2.25,5.23, body extent -3.75,-5.15 3.75,5.15, height 0.25
FCC_disclaimer [mm]
FP-0603YC104JAT2A_0603-MFG [mm]
  rrect13% 0.8x0.75 smd paste+0 mask+0: 1(-0.75,0) 2(0.75,0)
  silkscreen extent -0.87,-0.77 0.87,0.77, body extent -1.25,-0.58 1.25,0.58, height 0.25
FP-831-87-004-10-001101_CONN_SOCKET_4-MFG [mm] "Recommended Land Pattern"
  rrect8% 1.2x1.2 hole 1 paste-2539.97 mask+0: 1(-3,0)
  round 1.2 hole 1 paste-2539.97 mask+0: 2(-1,0) 3(1,0) 4(3,0)
  silkscreen extent -4,-1.7 4,1.1, body extent -4,-1.27 4,1.1, height 4.2
FP-APXJ160ARA271MF80J_SMT_CAP_6MM6_6MM6-MFG [mm] "Recommended Land Pattern"
  rrect6% 3.5x1.6 smd paste+0 mask+0: 1(-2.7,0) 2(2.7,0)
  silkscreen extent -5.12,-3.4 3.4,3.4, body extent -4.7,-3.65 4.7,3.65, height 0.25
FP-CGA1206X7R475M101NT_1206-IPC_C [mm]
  rrect9% 1.155x1.706 smd paste+0 mask+0: 1(-1.276,0) 2(1.276,0)
  silkscreen extent -0.4,-0.9 0.4,0.9, body extent -1.6,-0.8 1.6,0.8, height 1.8
FP-CL10B223KB8NNNC_0603-IPC_C [mm]
  rrect13% 0.758x0.812 smd paste+0 mask+0: 1(-0.627,0) 2(0.627,0)
  silkscreen extent -1.01,-0.85 1.01,0.85, body extent -1.11,-0.55 1.11,0.55, height 0.25
FP-CRCW0402-e3-MFG [mm]
  rect 0.6x0.6 smd paste+0 mask+0: 1(-0.525,0) 2(0.525,0)
  silkscreen extent -0.53,-0.7 0.53,0.7, body extent -0.92,-0.4 0.92,0.4, height 0.25
FP-D1LPC0402CJUMPF-T10_0402-MFG [mm]
  rrect17% 0.6x0.6 smd paste+0 mask+0: 1(-0.5,0) 2(0.5,0)
  silkscreen extent -0.6,-0.67 0.6,0.67, body extent -0.5,-0.25 0.5,0.25, height 0.45
FP-EMK325ABJ476KMHP_1210-MFG [mm]
  rrect8% 1.25x2.5 smd paste+0 mask+0: 1(-1.7,0) 2(1.7,0)
  silkscreen extent -0.7,-1.4 0.7,1.4, body extent -1.6,-1.25 1.6,1.25, height 2.8
FP-JR0805X35E_0805-MFG [mm]
  rrect7% 1.4x1.44 smd paste+0 mask+0: 1(-1.1,0) 2(1.1,0)
  silkscreen extent 0,-0.72 0,0.72, body extent -1,-0.63 1,0.63, height 0.55
FP-NRVB0540T1G_SOD-123-MFG [mil]
  rrect11% 36x48 smd paste+0 mask+0: 1(-64.5,0) 2(64.5,0)
  silkscreen extent -110,-35 32,35, body extent -72,-31 72,31, height 53
FP-RK73H1ETTP2871F_0402-MFG [mm]
  rrect33% 0.4x0.3 smd paste+0 mask+0: 1(-0.45,0) 2(0.45,0)
  silkscreen extent -0.64,-0.53 0.64,0.53, body extent -0.75,-0.38 0.75,0.38, height 0.25
FP-STPS30M100DJF-TR_PowerFlat6-MFG [mm]
  rrect15% 0.65x1.25 smd paste-1000 mask+0: 1(-1.905,-2.725) 2(-0.635,-2.725) 3(0.635,-2.725) 4(1.905,-2.725)
  round 3.687 smd paste-1000 mask+0: 5(0.252,0.748)
  Top Layer region: -2.3,3.35 -1.575,3.35 -1.575,2.8 -0.95,2.8 -0.95,3.35 -0.312,3.35 -0.312,2.8 0.312,2.8 0.312,3.35 0.95,3.35 0.95,2.8 1.575,2.8 1.575,3.35 2.3,3.35 2.3,-1.3 -2.3,-1.3 -2.3,3.35
  silkscreen extent -2.7,-4.02 2.7,3.17, body extent -2.6,-3.08 2.6,3.07, height 1
FP-XGL6060-332MEC_SMT_6MM51_6MM71-MFG [mm]
  rrect7% 1.43x5.5 smd paste+0 mask+0: 1(-2.02,0) 2(2.02,0)
  silkscreen extent -3.95,-3.45 3.35,3.45, body extent -3.45,-3.55 3.45,3.55, height 0.25
IEC_HotSurface_Small [mm]
  silkscreen extent -2.72,-2.36 2.72,2.35
KRL2012 [mm] "SUSUMU"
  rect 0.8x2.2 smd: 1(-0.7,0) 2(0.7,0)
  silkscreen extent -0.2,-1.35 0.2,1.35, body extent -0.72,-1.1 0.72,1.1, height 0.7
Pb-Free_Overlay_Medium [mm]
  silkscreen extent -2.41,-2.41 2.41,2.41
RDX0007A-MFG [mm]
  round 1.025 smd paste-1000 mask-1000: 1(-1.312,1.312)
  rrect13% 1.5x2.3 smd paste-1000 mask-1000: 2(-1.15,-0.675) 3(1.15,-0.675)
  round 0.991 smd paste-1000 mask-1000: 4(1.281,1.276)
  rrect45% 0.22x0.6 smd paste+0 mask-1000: 5(0.5,1.9) 6(0,1.9) 7(-0.5,1.9)
  Top Layer region: 1.9,1.8 1.892,1.838 1.871,1.871 1.838,1.892 1.8,1.9 1.8,1.9 0.925,1.9 0.887,1.892 0.854,1.871 0.833,1.838 0.825,1.8 0.825,1.8 0.825,1.634 0.818,1.596 0.796,1.563 0.796,1.563 0.507,1.274 0.474,1.252 0.436,1.245 0.436,1.245 0.39,1.245 0.352,1.237 0.319,1.216 0.298,1.183 0.29,1.145 0.29,1.145 0.29,0.825 0.298,0.787 0.319,0.754 0.352,0.733 0.39,0.725 0.39,0.725 1.8,0.725 1.838,0.733 1.871,0.754 1.892,0.787 1.9,0.825 1.9,0.825
  Top Layer region: -1.9,1.8 -1.887,1.85 -1.85,1.887 -1.8,1.9 -1.8,1.9 -0.925,1.9 -0.887,1.892 -0.854,1.871 -0.833,1.838 -0.825,1.8 -0.825,1.8 -0.825,1.634 -0.818,1.596 -0.796,1.563 -0.796,1.563 -0.507,1.274 -0.474,1.252 -0.436,1.245 -0.436,1.245 -0.39,1.245 -0.34,1.232 -0.303,1.195 -0.29,1.145 -0.29,1.145 -0.29,0.825 -0.298,0.787 -0.319,0.754 -0.352,0.733 -0.39,0.725 -0.39,0.725 -1.8,0.725 -1.838,0.733 -1.871,0.754 -1.892,0.787 -1.9,0.825 -1.9,0.825
  Keep-Out Layer region: -0.2,0.675 0.2,0.675 0.2,1.295 -0.2,1.295
  silkscreen extent -2.52,-2.17 2.07,2.37, body extent -1.65,-2 1.65,2, height 2.1
RRX0029B-MFG [mm]
  rrect40% 0.267x0.25 smd paste+0 mask-1000: 1(-3.066,2.25) 2(-3.066,1.75)
  rrect40% 0.6x0.25 smd paste+0 mask+0: 3(-2.9,1.25) 4(-2.9,0.25) 5(-2.9,-0.25) 6(-2.9,-1.25) 7(-2.9,-1.75) 8(-2.9,-2.25) 17(2.9,-1.75) 18(2.9,-1.25) 19(2.9,-0.75)
  rrect40% 0.25x0.6 smd paste+0 mask+0: 9(-2,-2.9) 10(-1.5,-2.9) 11(-1,-2.9) 12(0,-2.9) 13(0.5,-2.9) 14(1,-2.9) 15(1.5,-2.9) 16(2,-2.9) 23(2,2.9) 24(1.5,2.9) 25(1,2.9) 26(0.5,2.9)
  rrect40% 0.293x0.25 smd paste+0 mask-1000: 20(3.054,0.75) 21(3.054,1.25) 22(3.054,1.75)
  rrect40% 0.25x0.258 smd paste+0 mask-1000: 27(-1,3.071) 28(-1.5,3.071) 29(-2,3.071)
  rrect6% 3.125x1.584 smd paste-1000 mask+0: 30(0.037,-1.308)
  rrect11% 3.465x2.1 smd paste-1000 mask-1000: ""(1.537,1.12)
  Top Layer region: -3.27,3.22 -3.263,3.245 -3.245,3.263 -3.22,3.27 -3.22,3.27 -0.605,3.27 -0.586,3.266 -0.57,3.255 -0.559,3.239 -0.555,3.22 -0.555,3.22 -0.555,0.534 -0.564,0.488 -0.59,0.449 -0.629,0.423 -0.675,0.414 -0.675,0.414 -2.034,0.414 -2.08,0.423 -2.119,0.449 -2.145,0.488 -2.154,0.534 -2.154,0.534 -2.154,0.641 -2.158,0.66 -2.169,0.676 -2.185,0.687 -2.204,0.691 -2.204,0.691 -2.3,0.691 -2.346,0.7 -2.385,0.726 -2.411,0.765 -2.42,0.811 -2.42,0.811 -2.42,1.505 -2.427,1.53 -2.445,1.548 -2.47,1.555 -2.47,1.555 -3.15,1.555 -3.196,1.564 -3.235,1.59 -3.261,1.629 -3.27,1.675 -3.27,1.675
  silkscreen extent -3.88,-3.05 3.05,3.05, body extent -3,-3 3,3, height 1
SM_RADIAL_D [mm] "6.3 x 5.8mm:  Panasonic D"
  rect 3.2x1.6 smd: 1(-2.5,0) 2(2.5,0)
  silkscreen extent -3.4,-3.4 3.4,3.4, body extent -3.4,-3.4 3.4,3.4, height 6.1
SOD-123 [mm] "On Semi recommended land pattern"
  rect 0.915x1.22 smd: 1(-1.637,0) 2(1.637,0)
  silkscreen extent -2.74,-1.17 2.03,1.17, body extent -1.93,-0.9 1.93,0.9, height 1.35
VBE0015A-MFG#1 [mm]
  round 0.265 smd paste+0 mask-1000: 1(-1.675,2.875) 11(1.675,2.875)
  rrect40% 0.7x0.25 smd paste+0 mask-1000: 2(-1.85,2.325) 3(-1.85,1.825) 4(-1.85,1.325) 5(-1.85,0.825) 8(1.85,1.325) 9(1.85,1.825) 10(1.85,2.325)
  rrect11% 1.9x3.95 smd paste-1000 mask-1000: 6(-1.3,-1.525)
  rect 1.9x3.95 smd paste-1000 mask-1000: 7(1.3,-1.525)
  rrect40% 0.25x0.7 smd paste+0 mask-1000: 12(0.575,3.1) 13(0.075,3.1) 14(-0.425,3.1) 15(-0.925,3.1)
  Top Layer region: -2.15,2.7 -2.169,2.704 -2.185,2.715 -2.196,2.731 -2.2,2.75 -2.2,2.75 -2.2,2.9 -2.193,2.925 -2.175,2.943 -2.15,2.95 -2.15,2.95 -1.85,2.95 -1.812,2.958 -1.779,2.979 -1.758,3.012 -1.75,3.05 -1.75,3.05 -1.75,3.4 -1.746,3.419 -1.735,3.435 -1.719,3.446 -1.7,3.45 -1.7,3.45 -1.55,3.45 -1.531,3.446 -1.515,3.435 -1.504,3.419 -1.5,3.4 -1.5,3.4 -1.5,2.75 -1.504,2.731 -1.515,2.715 -1.531,2.704 -1.55,2.7 -1.55,2.7
  Top Layer region: 2.15,2.7 2.169,2.704 2.185,2.715 2.196,2.731 2.2,2.75 2.2,2.75 2.2,2.9 2.193,2.925 2.175,2.943 2.15,2.95 2.15,2.95 1.85,2.95 1.812,2.958 1.779,2.979 1.758,3.012 1.75,3.05 1.75,3.05 1.75,3.4 1.746,3.419 1.735,3.435 1.719,3.446 1.7,3.45 1.7,3.45 1.55,3.45 1.531,3.446 1.515,3.435 1.504,3.419 1.5,3.4 1.5,3.4 1.5,2.75 1.504,2.731 1.515,2.715 1.531,2.704 1.55,2.7 1.55,2.7
  silkscreen extent -2.95,-3.55 2.35,3.82, body extent -2.35,-3.6 2.35,3.55, height 0.25
VBE0015A-MFG#2 [mm]
  round 0.265 smd paste+0 mask-1000: 1(-1.675,2.875) 11(1.675,2.875)
  rrect40% 0.7x0.25 smd paste+0 mask-1000: 2(-1.85,2.325) 3(-1.85,1.825) 4(-1.85,1.325) 5(-1.85,0.825) 8(1.85,1.325) 9(1.85,1.825) 10(1.85,2.325)
  rrect11% 1.9x3.95 smd paste-1000 mask-1000: 6(-1.3,-1.525) 7(1.3,-1.525)
  rrect40% 0.25x0.7 smd paste+0 mask-1000: 12(0.575,3.1) 13(0.075,3.1) 14(-0.425,3.1) 15(-0.925,3.1)
  Top Layer region: 2.15,2.7 2.169,2.704 2.185,2.715 2.196,2.731 2.2,2.75 2.2,2.75 2.2,2.9 2.193,2.925 2.175,2.943 2.15,2.95 2.15,2.95 1.85,2.95 1.812,2.958 1.779,2.979 1.758,3.012 1.75,3.05 1.75,3.05 1.75,3.4 1.746,3.419 1.735,3.435 1.719,3.446 1.7,3.45 1.7,3.45 1.55,3.45 1.531,3.446 1.515,3.435 1.504,3.419 1.5,3.4 1.5,3.4 1.5,2.75 1.504,2.731 1.515,2.715 1.531,2.704 1.55,2.7 1.55,2.7
  Top Layer region: -2.15,2.7 -2.169,2.704 -2.185,2.715 -2.196,2.731 -2.2,2.75 -2.2,2.75 -2.2,2.9 -2.193,2.925 -2.175,2.943 -2.15,2.95 -2.15,2.95 -1.85,2.95 -1.812,2.958 -1.779,2.979 -1.758,3.012 -1.75,3.05 -1.75,3.05 -1.75,3.4 -1.746,3.419 -1.735,3.435 -1.719,3.446 -1.7,3.45 -1.7,3.45 -1.55,3.45 -1.531,3.446 -1.515,3.435 -1.504,3.419 -1.5,3.4 -1.5,3.4 -1.5,2.75 -1.504,2.731 -1.515,2.715 -1.531,2.704 -1.55,2.7 -1.55,2.7
  silkscreen extent -2.35,-3.55 2.35,4.17, body extent -2.35,-3.6 2.35,3.55, height 0.25
WE-HCB_1890 [mm] "WURTH ELEKTRONIK"
  rect 6x12.45 smd: 1(-6.65,0) 2(6.65,0)
  silkscreen extent -9.7,-9.4 9.7,9.4, body extent -9.65,-9.35 9.65,9.35, height 9.2
WEEE_Minimum [mm] "WEEElie bin"
  silkscreen extent -2.42,-4.38 2.52,2.65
